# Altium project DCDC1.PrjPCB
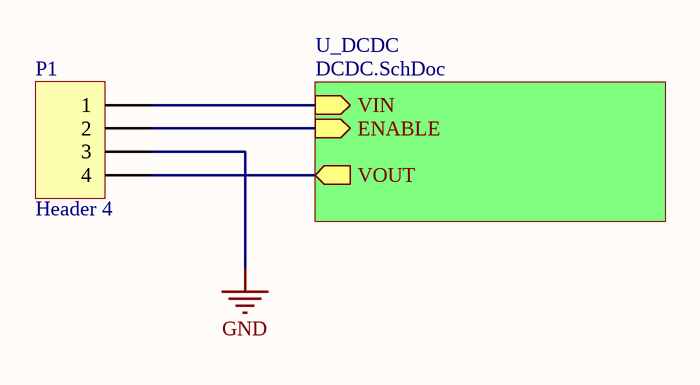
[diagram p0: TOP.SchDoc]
2 sheets, 11 parts. Net scope: hierarchical (ports join the sheet entries above them; power ports are global).
Board file: DCDC.PcbDoc
Sheets:
  TOP.SchDoc
    U_DCDC = DCDC.SchDoc

## Sheet TOP.SchDoc
size A4

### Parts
P1  Header 4  [HDR1X4]

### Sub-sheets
U_DCDC = DCDC.SchDoc: VIN (in), ENABLE (in), VOUT (out)

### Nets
GND: P1.3
ENA: P1.2 ; sheet U_DCDC/ENABLE
VIN: P1.1 ; sheet U_DCDC/VIN
VOUT: P1.4 ; sheet U_DCDC/VOUT

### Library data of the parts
P1 = Header 4: Header, 4-Pin

## Sheet DCDC.SchDoc
size A4
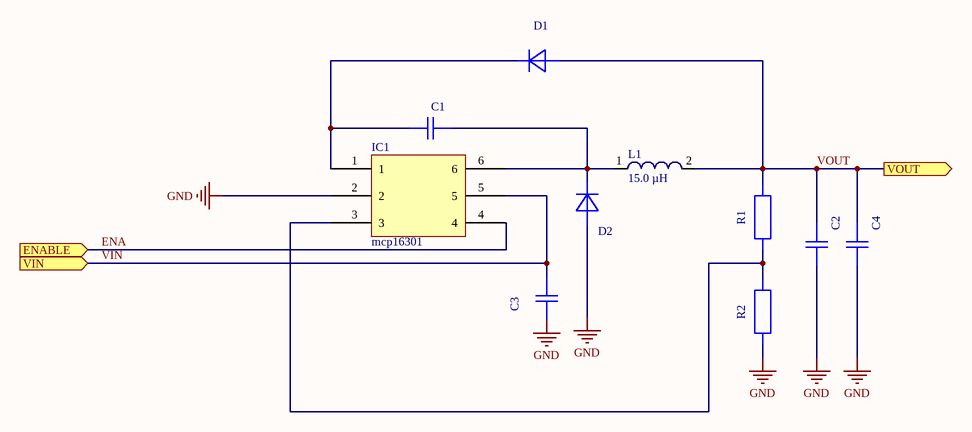
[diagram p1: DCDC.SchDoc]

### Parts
C1  C02X60Y0A1  [SMD 0603]  (value not drawn)
C2  C02X60Y0A1  [6-0805_M]  (value not drawn)
C3  C02X60Y0A1  [C1206]  (value not drawn)
C4  C02X60Y0A1  [6-0805_M]  (value not drawn)
D1  D02X125Y0A0  [D02X125Y0A0]  (value not drawn)
D2  D02X125Y0A0  [D02X125Y0A0]  (value not drawn)
IC1  mcp16301  [SOT23-6_L]
L1  15.0 µH  [WE-TPC 3816, S]
R1  R02X60Y0A0  [R02X60Y0A0]  (value not drawn)
R2  R02X60Y0A0  [R02X60Y0A0]  (value not drawn)

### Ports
ENABLE (in), VIN (in), VOUT (out)

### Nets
GND: IC1.2
ENA: IC1.4 ; port ENABLE
VIN: IC1.5 ; port VIN
VOUT: L1.2 ; port VOUT
NetIC1_6: IC1.6 L1.1

Not connected (* = marked no-connect by the designer): C1 1 2; C2 1 2; C3 1 2; C4 1 2; D1 A K; D2 A K; IC1 1 3; R1 1 2; R2 1 2

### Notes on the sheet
- Labels drawn without touching a wire or pin: GND

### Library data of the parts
C1-C4 = C1210/10U/16V/X7R: PART DESCE: CHIP-CAP. 10u  10% 16 V  X7R; TYPE: GRM32DR71C106KA01L; GR: C7; PCB DECAL: C02X136Y0A0; MFG.#1: MURATA; SUPP.#1: DIGIKEY; SUPP.ART.#1: 490-1875-1-ND; Geometry.Height: 0.99mm
D1 D2 = D_LL4148/MMELF: PART DESCE: DIODE MINI MELF; TYPE: LL4148; GR: D; VALUE: 75V/0A2; MFG.#1: ITT; SUPP.#1: BUERKLIN; SUPP.ART.#1: 24 S 3460; Geometry.Height: 3.6mm
L1 = WE-TPC 3816, S, 744031150: SMD Shielded Tiny Power Inductor WE-TPC, L=15.0 µH
R1 R2 = R06/1M: PART DESCE: CHIP RESISTOR 1M OHM 0.063W 1% 0603 SMD; Geometry.Height: 0.45mm; VALUE: 1M; MFG.#1: MULTICOMP; GR: R4; SUPP.#1: FARNELL; SUPP.ART.#1: 9330410

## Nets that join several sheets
GND: TOP (P1.3), DCDC (IC1.2)
ENA: TOP (P1.2), DCDC (IC1.4)
VIN: TOP (P1.1), DCDC (IC1.5)
VOUT: TOP (P1.4), DCDC (L1.2)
